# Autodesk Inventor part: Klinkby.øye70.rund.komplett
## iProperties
Created: 2009-07
Part Number: Klinkby.øye70.rund.komplett
Document SubType Name: Modeling
Designer: TB
Mass: 1007.93 g
Surface Area: 1068.08 cm^2
Volume: 1007.93 cm^3
Density: 1 g/cm^3
Author: TB
